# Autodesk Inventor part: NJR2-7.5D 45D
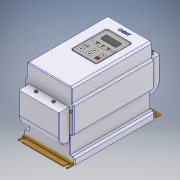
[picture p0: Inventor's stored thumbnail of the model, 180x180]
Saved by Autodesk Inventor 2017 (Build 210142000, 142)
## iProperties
Part Number: NJR2-7.5D 45D
Material: Типовые
Document SubType Name: Modeling
Designer: RSagdiev
Density: 1 g/cm^3
Appearance: По умолчанию
Author: RSagdiev
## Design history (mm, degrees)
sketch "Эскиз1"
  geometry: L1 (0, 0)-(14.471, 0) reference; L2 (0, 0)-(0, 21.118) reference; L3 (0, 0)-(230, 0); L4 (230, 0)-(230, 20); L5 (230, 190)-(0, 190); L6 (0, 190)-(0, 150); L7 (230, 20)-(0, 20); L8 (230, 70)-(0, 70); L9 (230, 70)-(230, 150); L10 (230, 20)-(230, 70); L11 (0, 70)-(0, 20); L12 (0, 20)-(0, 0); L13 (230, 150)-(0, 150); L14 (230, 150)-(230, 190); L15 (0, 150)-(0, 70)
  constraints: 30 end point, 17 parallel, 14 perpendicular, 3 horizontal, 2 vertical, 1 point on line
  dimensions: "d0" = 230 distance of L5.end L5.start; "d1" = 190 distance of L5.start L3.end; "d2" = 20 distance between parallel lines of L3 L7; "d3" = 50 distance between parallel lines of L8 L7; "d4" = 80 distance between parallel lines of L13 L8
extrude "Выдавливание1" new body sketch "Эскиз1" stored distance "d5" = 145; taper "d6" = 0 deg
extrude "Выдавливание2" join sketch "Эскиз1" stored distance "d7" = 120; taper "d8" = 0 deg
extrude "Выдавливание3" join sketch "Эскиз1" stored distance "d9" = 140; taper "d10" = 0 deg
extrude "Выдавливание4" join sketch "Эскиз1" stored distance "d11" = 130; taper "d12" = 0 deg
chamfer "Фаска1" distance "d13" = 5; stored, may be unused: second distance "d14" = 2, angle "d15" = 45 deg
sketch "Эскиз2"
  geometry: L1 (249, 0)-(234, 0); L2 (233, 1)-(233, 3); L3 (232, 4)-(-2, 4); L4 (-3, 3)-(-3, 1); L5 (-4, 0)-(-19, 0); L6 (230, 15)-(230, 0) reference; L7 (230, 0)-(0, 0) reference; L8 (0, 0)-(0, 15) reference; L9 (249, 3)-(236, 3); L10 (232, 7)-(-2, 7); L11 (-6, 3)-(-19, 3); L12 (-19, 0)-(-19, 3); L13 (249, 3)-(249, 0); A1 r 1 centre (-4, 1) between (-4, 0) and (-3, 1); A2 r 1 centre (-2, 3) between (-2, 4) and (-3, 3); A3 r 1 centre (234, 1) between (233, 1) and (234, 0); A4 r 1 centre (232, 3) between (233, 3) and (232, 4); A5 r 4 centre (232, 3) between (236, 3) and (232, 7); A6 r 4 centre (-2, 3) between (-2, 7) and (-6, 3); 6 further points
  constraints: 20 end point, 12 point on circle, 10 point on line, 8 tangent, 6 centre point, 4 perpendicular, 3 equal radius, 1 horizontal, 1 parallel, 4 other
  dimensions: "d16" = 4 distance of point (233, 0) point (233, 4); "d17" = 3 distance between parallel lines of L2 L6; "d18" = 4 distance between parallel lines of L7 L3; "d19" = 16 distance of point (233, 0) L1.start; "d20" = 16 distance of point (-3, 0) L5.end (= d19); "d21" = 4 distance of point (-3, 4) point (-3, 0) (derived); "d22" = 3 distance between parallel lines of L4 L8 (= d17); "d23" = 268 distance of L5.end L1.start (derived); "d24" = 1 radius of A1; "d25" = 3 distance between parallel lines of L1 L9
extrude "Выдавливание5" new body sketch "Эскиз2" stored distance "d26" = 143; taper "d27" = 0 deg
sketch "Эскиз4"
  geometry: L1 (260, 138)-(-30, 138); L2 (-30, 138)-(-30, 50); L3 (-30, 50)-(260, 50); L4 (260, 50)-(260, 138); L5 (0, 70)-(230, 70) reference; L6 (230, 190)-(230, 150) reference; L7 (230, 0)-(0, 0) reference; L8 (0, 150)-(230, 150) reference
  constraints: 8 end point, 2 parallel, 1 horizontal, 1 perpendicular
  dimensions: "d28" = 290 distance between parallel lines of L2 L4; "d187" = 20 distance between parallel lines of L5 L3; "d188" = 30 distance between parallel lines of L6 L4; "d189" = 50 distance between parallel lines of L7 L3 (derived); "d190" = 12 distance between parallel lines of L8 L1
extrude "Выдавливание6" join sketch "Эскиз4" stored distance "d32" = 115; taper "d33" = 0 deg
fillet "Сопряжение1" dims "d35" = 25
sketch "Эскиз5" dims "d44" = 10
  geometry: L1 (115, 0)-(0, 0) reference; L2 (115, 30)-(115, 0) reference; L3 (115, 30)-(0, 30) reference; L4 (0, 0)-(0, 30) reference; L5 (0, -260)-(115, -260) reference; L6 (0, -230)-(115, -230) reference; L7 (0, -260)-(0, -230) reference; L8 (115, -230)-(115, -260) reference; C1 r 4 at (20, 20); C2 r 4 at (35.833, 20); C3 r 4 at (51.667, 20); C4 r 4 at (67.5, 20); C5 r 4 at (83.333, 20); C6 r 4 at (99.167, 20); 1 further point
  constraints: 6 centre point, 1 horizontal, 10 other
  dimensions: "d36" = 8 diameter of C1; "d37" = 115 distance between parallel lines of L2 L4 (derived); "d38" = 20 distance from line of C1.centre L4; "d41" = 15.83333 distance of C1.centre C2.centre (= -0.166667 x d38 + 0.166667 x d37)
  node "Спроецированная петля1"
extrude "Выдавливание7" cut sketch "Эскиз5" distance "d46" = 20; taper "d47" = 0 deg
extrude "Выдавливание8" new body sketch "Эскиз5" distance "d48" = 20; taper "d49" = 0 deg
sketch "Эскиз6" dims "d50" = 12, "d56" = 10
  geometry: L1 (0, 6)-(5.196, 3); L2 (5.196, 3)-(5.196, -3); L3 (5.196, -3)-(0, -6); L4 (0, -6)-(-5.196, -3); L5 (-5.196, -3)-(-5.196, 3); L6 (-5.196, 3)-(0, 6); L7 (95, 10)-(-20, 10) reference; L8 (15.833, 6)-(21.029, 3); L9 (21.029, 3)-(21.029, -3); L10 (21.029, -3)-(15.833, -6); L11 (15.833, -6)-(10.637, -3); L12 (10.637, -3)-(10.637, 3); L13 (10.637, 3)-(15.833, 6); L14 (31.667, 6)-(36.863, 3); L15 (36.863, 3)-(36.863, -3); L16 (36.863, -3)-(31.667, -6); L17 (31.667, -6)-(26.471, -3); L18 (26.471, -3)-(26.471, 3); L19 (26.471, 3)-(31.667, 6); L20 (47.5, 6)-(52.696, 3); L21 (52.696, 3)-(52.696, -3); L22 (52.696, -3)-(47.5, -6); L23 (47.5, -6)-(42.304, -3); L24 (42.304, -3)-(42.304, 3); L25 (42.304, 3)-(47.5, 6); L26 (63.333, 6)-(68.529, 3); L27 (68.529, 3)-(68.529, -3); L28 (68.529, -3)-(63.333, -6); L29 (63.333, -6)-(58.137, -3); L30 (58.137, -3)-(58.137, 3); L31 (58.137, 3)-(63.333, 6); L32 (79.167, 6)-(84.363, 3); L33 (84.363, 3)-(84.363, -3); L34 (84.363, -3)-(79.167, -6); L35 (79.167, -6)-(73.971, -3); L36 (73.971, -3)-(73.971, 3); L37 (73.971, 3)-(79.167, 6); 13 further points
  constraints: 72 end point, 6 coincident, 6 horizontal, 6 vertical alignment, 95 other
  dimensions: "d53" = 15.83333 distance of point (0, 0) point (15.833, 0) (= -0.166667 x d38 + 0.166667 x d37)
extrude "Выдавливание9" join sketch "Эскиз6" distance "d58" = 5; taper "d59" = 0 deg
sketch "Эскиз7" dims "d185" = 10
  geometry: L1 (2.964, 2.686)-(3.808, -1.224); L2 (3.808, -1.224)-(0.844, -3.91); L3 (0.844, -3.91)-(-2.964, -2.686); L4 (-2.964, -2.686)-(-3.808, 1.224); L5 (-3.808, 1.224)-(-0.844, 3.91); L6 (-0.844, 3.91)-(2.964, 2.686); L7 (95, 10)-(-20, 10) reference; L8 (23.764, 2.686)-(24.608, -1.224); L9 (24.608, -1.224)-(21.644, -3.91); L10 (21.644, -3.91)-(17.836, -2.686); L11 (17.836, -2.686)-(16.992, 1.224); L12 (16.992, 1.224)-(19.956, 3.91); L13 (19.956, 3.91)-(23.764, 2.686); L14 (44.564, 2.686)-(45.408, -1.224); L15 (45.408, -1.224)-(42.444, -3.91); L16 (42.444, -3.91)-(38.636, -2.686); L17 (38.636, -2.686)-(37.792, 1.224); L18 (37.792, 1.224)-(40.756, 3.91); L19 (40.756, 3.91)-(44.564, 2.686); L20 (65.364, 2.686)-(66.208, -1.224); L21 (66.208, -1.224)-(63.244, -3.91); L22 (63.244, -3.91)-(59.436, -2.686); L23 (59.436, -2.686)-(58.592, 1.224); L24 (58.592, 1.224)-(61.556, 3.91); L25 (61.556, 3.91)-(65.364, 2.686); L26 (86.164, 2.686)-(87.008, -1.224); L27 (87.008, -1.224)-(84.044, -3.91); L28 (84.044, -3.91)-(80.236, -2.686); L29 (80.236, -2.686)-(79.392, 1.224); L30 (79.392, 1.224)-(82.356, 3.91); L31 (82.356, 3.91)-(86.164, 2.686); L32 (106.964, 2.686)-(107.808, -1.224); L33 (107.808, -1.224)-(104.844, -3.91); L34 (104.844, -3.91)-(101.036, -2.686); L35 (101.036, -2.686)-(100.192, 1.224); L36 (100.192, 1.224)-(103.156, 3.91); L37 (103.156, 3.91)-(106.964, 2.686); C1 r 6 at (0, 0) reference; A1 r 4 centre (0, 0) between (2.964, 2.686) and (-2.964, -2.686); A2 r 4 centre (20.8, 0) between (23.764, 2.686) and (17.836, -2.686); A3 r 4 centre (41.6, 0) between (44.564, 2.686) and (38.636, -2.686); A4 r 4 centre (62.4, 0) between (65.364, 2.686) and (59.436, -2.686); A5 r 4 centre (83.2, 0) between (86.164, 2.686) and (80.236, -2.686); A6 r 4 centre (104, 0) between (106.964, 2.686) and (101.036, -2.686); 1 further point
  constraints: 72 end point, 36 point on circle, 6 centre point, 5 equal length, 1 horizontal, 70 other
  dimensions: "d179" = 2 radial gap between concentric circles of C1 A1; "d182" = 20.8 distance of L1.start L8.start
extrude "Выдавливание10" cut sketch "Эскиз7" distance "d66" = 1.5; taper "d67" = 0 deg
fillet "Сопряжение2" dims "d68" = 2
sketch "Эскиз8"
  geometry: L1 (0, -268)-(143, -268) reference; L2 (143, 0)-(0, 0) reference; L3 (143, 0)-(143, -15) reference; L4 (0, -15)-(0, 0) reference; L5 (7.5, -9)-(7.5, -14); L6 (135.5, -9)-(135.5, -14); L7 (7.5, -9)-(135.5, -9); L8 (7.5, -259)-(7.5, -268); L9 (4, -259)-(4, -268); L10 (11, -268)-(11, -259); L11 (7.5, -9)-(7.5, -259); L12 (7.5, -259)-(135.5, -259); L13 (135.5, -9)-(135.5, -259); L14 (135.5, -259)-(135.5, -268); L15 (132, -259)-(132, -268); L16 (139, -268)-(139, -259); A1 r 3.5 centre (7.5, -9) between (10.779, -10.225) and (4.221, -10.225); A2 r 5 centre (7.5, -14) between (4.221, -10.225) and (10.779, -10.225); A3 r 3.5 centre (135.5, -9) between (138.779, -10.225) and (132.221, -10.225); A4 r 5 centre (135.5, -14) between (132.221, -10.225) and (138.779, -10.225); A5 r 3.5 centre (7.5, -259) between (11, -259) and (4, -259); A6 r 3.5 centre (7.5, -268) between (4, -268) and (11, -268); A7 r 3.5 centre (135.5, -259) between (139, -259) and (132, -259); A8 r 3.5 centre (135.5, -268) between (132, -268) and (139, -268); 5 further points
  constraints: 28 end point, 16 point on circle, 8 centre point, 8 tangent, 4 vertical, 3 coincident, 2 horizontal, 2 midpoint, 2 parallel, 2 perpendicular, 2 point on line
  dimensions: "d69" = 128 distance of point (135.5, -9) point (7.5, -9); "d70" = 250 distance of L8.start point (7.5, -9); "d71" = 268 distance between parallel lines of L1 L2 (derived); "d72" = 9 distance from line of L2 point (7.5, -9) (= -0.5 x d70 + 0.5 x d71); "d73" = 143 distance between parallel lines of L3 L4 (derived); "d74" = 7.5 distance from line of L4 point (7.5, -9) (= -0.5 x d69 + 0.5 x d73); "d75" = 7 diameter of A1; "d76" = 10 diameter of A2; "d77" = 5 distance of L5.start L5.end; "d78" = 7 diameter of A3; "d79" = 10 diameter of A4; "d80" = 5 distance of L6.start L6.end; "d81" = 7 diameter of A6; "d82" = 7 diameter of A8
extrude "Выдавливание11" cut sketch "Эскиз8" distance "d83" = 5.5; taper "d84" = 0 deg
fillet "Сопряжение3" dims "d85" = 2
sketch "Эскиз9"
  geometry: L1 (125, 0)-(5, 0); L2 (5, 226)-(125, 226); L3 (33, 193)-(97, 193); L4 (100, 190)-(100, 96); L5 (97, 93)-(33, 93); L6 (30, 96)-(30, 190); L7 (97, 195)-(33, 195); L8 (28, 190)-(28, 96); L9 (33, 91)-(97, 91); L10 (102, 96)-(102, 190); L11 (125, 226)-(125, 0); L12 (5, 0)-(5, 226); A1 r 3 centre (33, 190) between (33, 193) and (30, 190); A2 r 3 centre (97, 190) between (100, 190) and (97, 193); A3 r 3 centre (97, 96) between (97, 93) and (100, 96); A4 r 3 centre (33, 96) between (30, 96) and (33, 93); A5 r 5 centre (33, 190) between (33, 195) and (28, 190); A6 r 5 centre (33, 96) between (28, 96) and (33, 91); A7 r 5 centre (97, 96) between (97, 91) and (102, 96); A8 r 5 centre (97, 190) between (102, 190) and (97, 195); 4 further points
  constraints: 24 end point, 16 point on circle, 8 centre point, 8 tangent, 6 point on line, 4 parallel, 3 equal radius, 2 perpendicular, 1 horizontal, 7 other
  dimensions: "d86" = 70 distance of point (100, 93) point (30, 93); "d87" = 100 distance of point (100, 193) point (100, 93); "d90" = 33 distance between parallel lines of L2 L3 (computed from d89, d87); "d92" = 3 radius of A1; "d93" = 2 distance between parallel lines of L3 L7
extrude "Выдавливание12" cut sketch "Эскиз9" distance "d94" = 25; taper "d95" = 0 deg
extrude "Выдавливание13" new body sketch "Эскиз9" distance "d96" = 25; taper "d97" = 0 deg
sketch "Эскиз10"
  geometry: L1 (30, 190)-(30, 150.574); L2 (33, 93)-(97, 93); L3 (100, 96)-(100, 150.574); L4 (97, 193)-(33, 193); L5 (97, 193)-(33, 193) reference; L6 (30, 190)-(30, 96) reference; L7 (30, 150.574)-(30, 96); L8 (100, 150.574)-(100, 190); L9 (45.628, 161.287)-(84.628, 161.287); L10 (87.628, 164.287)-(87.628, 176.287); L11 (84.628, 179.287)-(45.628, 179.287); L12 (42.628, 176.287)-(42.628, 164.287); L13 (42.628, 161.287)-(87.628, 179.287); L14 (87.628, 161.287)-(42.628, 179.287); A1 r 3 centre (33, 96) between (30, 96) and (33, 93); A2 r 3 centre (97, 96) between (97, 93) and (100, 96); A3 r 3 centre (97, 190) between (100, 190) and (97, 193); A4 r 3 centre (33, 190) between (33, 193) and (30, 190); A5 r 55 centre (65, 193) between (30, 150.574) and (100.197, 150.737); A6 r 3 centre (45.628, 176.287) between (45.628, 179.287) and (42.628, 176.287); A7 r 3 centre (45.628, 164.287) between (42.628, 164.287) and (45.628, 161.287); A8 r 3 centre (84.628, 176.287) between (87.628, 176.287) and (84.628, 179.287); A9 r 3 centre (84.628, 164.287) between (84.628, 161.287) and (87.628, 164.287); 2 further points
  constraints: 20 end point, 11 point on circle, 9 centre point, 9 point on line, 8 tangent, 3 equal radius, 3 midpoint, 2 parallel, 1 horizontal, 1 perpendicular
  dimensions: "d98" = 55 radius of A5; "d99" = 45 distance of L14.end L13.end; "d100" = 18 distance of L13.end L14.start; "d101" = 22.7132 distance from line of L4 point (65.128, 170.287); "d102" = 35.1281 distance from line of L1 point (65.128, 170.287); "d103" = 3 radius of A6 (derived)
extrude "Выдавливание14" cut sketch "Эскиз10" distance "d104" = 1; taper "d105" = 0 deg
sketch "Эскиз11"
  geometry: L1 (30, 150.574)-(30, 96) reference; L2 (33, 93)-(97, 93) reference; L3 (100, 96)-(100, 150.574) reference; L4 (30, 150.574)-(30, 96) reference; L5 (30, 123)-(100, 123); L6 (100, 96)-(100, 150.574) reference; L7 (30, 108)-(100, 108); L8 (33, 93)-(97, 93) reference; L9 (41.667, 93)-(41.667, 143.195); L10 (88.333, 93)-(88.333, 143.195); L11 (65, 93)-(65, 138); L12 (36.667, 128)-(46.667, 128); L13 (46.667, 128)-(46.667, 118); L14 (46.667, 118)-(36.667, 118); L15 (36.667, 118)-(36.667, 128); L16 (36.667, 128)-(46.667, 118); L17 (46.667, 128)-(36.667, 118); L18 (36.667, 113)-(46.667, 113); L19 (46.667, 113)-(46.667, 103); L20 (46.667, 103)-(36.667, 103); L21 (36.667, 103)-(36.667, 113); L22 (36.667, 113)-(46.667, 103); L23 (46.667, 113)-(36.667, 103); L24 (60, 128)-(70, 128); L25 (70, 128)-(70, 118); L26 (70, 118)-(60, 118); L27 (60, 118)-(60, 128); L28 (60, 128)-(70, 118); L29 (70, 128)-(60, 118); L30 (60, 113)-(70, 113); L31 (70, 113)-(70, 103); L32 (70, 103)-(60, 103); L33 (60, 103)-(60, 113); L34 (60, 113)-(70, 103); L35 (70, 113)-(60, 103); L36 (83.333, 128)-(93.333, 128); L37 (93.333, 128)-(93.333, 118); L38 (93.333, 118)-(83.333, 118); L39 (83.333, 118)-(83.333, 128); L40 (83.333, 128)-(93.333, 118); L41 (93.333, 128)-(83.333, 118); L42 (83.333, 113)-(93.333, 113); L43 (93.333, 113)-(93.333, 103); L44 (93.333, 103)-(83.333, 103); L45 (83.333, 103)-(83.333, 113); L46 (83.333, 113)-(93.333, 103); L47 (93.333, 113)-(83.333, 103); L48 (46.767, 128.1)-(36.567, 128.1); L49 (36.567, 128.1)-(36.567, 117.9); L50 (36.567, 117.9)-(46.767, 117.9); L51 (46.767, 117.9)-(46.767, 128.1); L52 (70.1, 128.1)-(59.9, 128.1); L53 (59.9, 128.1)-(59.9, 117.9); L54 (59.9, 117.9)-(70.1, 117.9); L55 (70.1, 117.9)-(70.1, 128.1); L56 (93.433, 128.1)-(83.233, 128.1); L57 (83.233, 128.1)-(83.233, 117.9); L58 (83.233, 117.9)-(93.433, 117.9); L59 (93.433, 117.9)-(93.433, 128.1); L60 (46.767, 113.1)-(36.567, 113.1); L61 (36.567, 113.1)-(36.567, 102.9); L62 (36.567, 102.9)-(46.767, 102.9); L63 (46.767, 102.9)-(46.767, 113.1); L64 (70.1, 113.1)-(59.9, 113.1)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; A1 r 55 centre (65, 193) between (30, 150.574) and (100, 150.574) reference; A2 r 3 centre (33, 96) between (30, 96) and (33, 93) reference; A3 r 3 centre (97, 96) between (97, 93) and (100, 96) reference; A4 r 55 centre (65, 193) between (30, 150.574) and (100, 150.574) reference; 8 further points
  constraints: 130 end point, 24 parallel, 16 midpoint, 16 point on line, 14 perpendicular, 7 horizontal, 4 point on circle, 1 vertical, 18 other
  dimensions: "d106" = 70 distance between parallel lines of L3 L1 (derived); "d107" = 45 distance from line of L2 L11.end (derived); "d108" = 15 distance between parallel lines of L7 L5 (= 0.333333 x d107); "d109" = 15 distance from line of L11.end L5 (= 0.333333 x d107); "d110" = 23.33333 distance between parallel lines of L11 L10 (= 0.333333 x d106); "d111" = 23.33333 distance between parallel lines of L11 L9 (= d110); "d112" = 10 distance of L13.end L14.end; "d113" = 10 distance of L12.end L13.end; "d114" = 10 distance of L19.end L20.end; "d115" = 10 distance of L18.end L19.end; "d116" = 10 distance of L25.end L26.end; "d117" = 10 distance of L24.end L25.end; "d118" = 10 distance of L31.end L32.end; "d119" = 10 distance of L30.end L31.end; "d120" = 10 distance of L37.end L38.end; "d121" = 10 distance of L36.end L37.end; "d122" = 10 distance of L43.end L44.end; "d123" = 10 distance of L42.end L43.end; "d124" = 0.1 distance between parallel lines of L12 L48; "d125" = 0.1 distance between parallel lines of L24 L52; "d126" = 0.1 distance between parallel lines of L36 L56; "d127" = 0.1 distance between parallel lines of L18 L60; "d128" = 0.1 distance between parallel lines of L30 L64; "d129" = 0.1 distance between parallel lines of L42 L68
extrude "Выдавливание15" cut sketch "Эскиз11" distance "d130" = 3; taper "d131" = 0 deg
sketch "Эскиз12"
  geometry: L1 (100, 96)-(100, 150.574) reference; L2 (50, 144.701)-(80, 144.701); C1 r 1.5 at (65, 144.701); C2 r 1.5 at (80, 144.701); C3 r 1.5 at (50, 144.701); C4 r 1.6 at (50, 144.701); C5 r 1.6 at (65, 144.701); C6 r 1.6 at (80, 144.701); A1 r 55 centre (65, 193) between (30, 150.574) and (100, 150.574) reference; 1 further point
  constraints: 6 centre point, 2 end point, 1 coincident, 1 horizontal, 1 midpoint
  dimensions: "d132" = 3 diameter of C1; "d133" = 3 diameter of C2; "d134" = 3 diameter of C3; "d135" = 48.29941 distance of A1.centre C1.centre; "d136" = 35 distance from line of L1 C1.centre; "d137" = 15 distance of C1.centre C2.centre; "d138" = 15 distance of C1.centre L2.start; "d139" = 0.1 radial gap between concentric circles of C3 C4; "d140" = 0.1 radial gap between concentric circles of C1 C5; "d141" = 0.1 radial gap between concentric circles of C2 C6
extrude "Выдавливание16" cut sketch "Эскиз12" distance "d142" = 3; taper "d143" = 0 deg
sketch "Эскиз13"
  geometry: L1 (45, 150.348)-(102.075, 150.348); L2 (102.075, 150.348)-(102.075, 146.701); L3 (102.075, 146.701)-(45, 146.701); L4 (45, 146.701)-(45, 150.348); C1 r 1.5 at (50, 144.701) reference; 1 further point
  constraints: 2 other
  dimensions: "d144" = 2 vertical distance of L3.end C1.centre; "d145" = 5 horizontal distance of C1.centre L3.end
feature "Рельеф1" sketch "Эскиз13" dims "d10" = 0, "d146" = 0.1, "d147" = 0
sketch "Эскиз14"
  geometry: L1 (36.734, 124.406)-(51.145, 124.406); L2 (51.145, 124.406)-(51.145, 120.906); L3 (51.145, 120.906)-(36.734, 120.906); L4 (36.734, 120.906)-(36.734, 124.406); L5 (38.873, 106.059)-(38.873, 109.559); L6 (38.873, 109.559)-(53.285, 109.559); L7 (53.285, 109.559)-(53.285, 106.059); L8 (53.285, 106.059)-(38.873, 106.059); L9 (84.699, 105.985)-(84.699, 109.485); L10 (84.699, 109.485)-(99.11, 109.485); L11 (99.11, 109.485)-(99.11, 105.985); L12 (99.11, 105.985)-(84.699, 105.985); L13 (85.21, 120.906)-(85.21, 124.406); L14 (85.21, 124.406)-(99.621, 124.406); L15 (99.621, 124.406)-(99.621, 120.906); L16 (99.621, 120.906)-(85.21, 120.906); 1 further point
  constraints: 8 other
feature "Рельеф2" dims "d10" = 0, "d148" = 0.1, "d149" = 0
feature "Рельеф3" dims "d10" = 0, "d150" = 0.1, "d151" = 0
feature "Рельеф4" dims "d10" = 0, "d152" = 0.1, "d153" = 0
feature "Рельеф5" dims "d10" = 0, "d154" = 0.1, "d155" = 0
sketch "Эскиз15" dims "d156" = 6, "d157" = 6
  geometry: L1 (60, 128)-(60, 118) reference; L2 (60, 118)-(70, 118) reference; L3 (70, 118)-(70, 128) reference; L4 (70, 128)-(60, 128) reference; L5 (60, 113)-(60, 103) reference; L6 (60, 103)-(70, 103) reference; L7 (70, 103)-(70, 113) reference; L8 (70, 113)-(60, 113) reference; L9 (60, 118)-(70, 128); L10 (60, 128)-(70, 118); L11 (60, 113)-(70, 103); L12 (70.1, 113.1)-(70.1, 102.9) reference; L13 (70.1, 113.1)-(60, 103); L14 (65.05, 126)-(67.573, 121.457); L15 (67.573, 121.457)-(62.377, 121.544); L16 (62.377, 121.544)-(65.05, 126); L17 (65.05, 105.05)-(62.452, 109.55); L18 (62.452, 109.55)-(67.648, 109.55); L19 (67.648, 109.55)-(65.05, 105.05); 5 further points
  constraints: 20 end point, 2 coincident, 2 midpoint, 2 perpendicular, 1 parallel, 1 vertical alignment, 19 other
  node "Спроецированная петля11"
  node "Спроецированная петля12"
feature "Рельеф6" dims "d10" = 0, "d158" = 0.1, "d159" = 0
feature "Рельеф7" dims "d10" = 0, "d160" = 0.1, "d161" = 0
sketch "Эскиз16"
  geometry: L1 (2, -30)-(113, -30) reference; L2 (0, 0)-(115, 0) reference; L3 (130, -10)-(0, -10); L4 (0, -28)-(0, -5) reference; L5 (113, 260)-(2, 260) reference; L6 (115, 230)-(0, 230) reference; L7 (115, 0)-(115, -28) reference; L8 (0, -28)-(0, 0) reference; L9 (0, 230)-(0, 258) reference; L10 (115, 258)-(115, 230) reference; C1 r 4 at (30, -10); C2 r 4 at (80, -10); C3 r 4 at (130, -10); A1 r 2 centre (2, -28) between (0, -28) and (2, -30) reference; A2 r 2 centre (113, -28) between (113, -30) and (115, -28) reference; A3 r 2 centre (113, 258) between (115, 258) and (113, 260) reference; A4 r 2 centre (2, 258) between (2, 260) and (0, 258) reference; 1 further point
  constraints: 3 centre point, 3 point on line, 2 end point, 1 horizontal
  dimensions: "d162" = 8 diameter of C1; "d163" = 8 diameter of C2; "d164" = 8 diameter of C3; "d166" = 20 distance from line of L3.start L1; "d167" = 50 distance of C2.centre L3.start; "d168" = 50 distance of C1.centre C2.centre
extrude "Выдавливание17" new body sketch "Эскиз16" distance "d169" = 3; taper "d170" = 0 deg
sketch "Эскиз17"
  geometry: L1 (-28, -20)-(83, -20) reference; L2 (-30, 10)-(85, 10) reference; L3 (0, 3)-(2.598, 1.5); L4 (2.598, 1.5)-(2.598, -1.5); L5 (2.598, -1.5)-(0, -3); L6 (0, -3)-(-2.598, -1.5); L7 (-2.598, -1.5)-(-2.598, 1.5); L8 (-2.598, 1.5)-(0, 3); L9 (50, 3)-(52.598, 1.5); L10 (52.598, 1.5)-(52.598, -1.5); L11 (52.598, -1.5)-(50, -3); L12 (50, -3)-(47.402, -1.5); L13 (47.402, -1.5)-(47.402, 1.5); L14 (47.402, 1.5)-(50, 3); L15 (100, 3)-(102.598, 1.5); L16 (102.598, 1.5)-(102.598, -1.5); L17 (102.598, -1.5)-(100, -3); L18 (100, -3)-(97.402, -1.5); L19 (97.402, -1.5)-(97.402, 1.5); L20 (97.402, 1.5)-(100, 3); L21 (83, 270)-(-28, 270) reference; L22 (85, 240)-(-30, 240) reference; L23 (85, 10)-(85, -18) reference; L24 (-30, -18)-(-30, 10) reference; L25 (-30, 240)-(-30, 268) reference; L26 (85, 268)-(85, 240) reference; C1 r 4 at (0, 0) reference; C2 r 4 at (50, 0) reference; C3 r 4 at (100, 0) reference; C4 r 4 at (50, 0) reference; A1 r 2 centre (-28, -18) between (-30, -18) and (-28, -20) reference; A2 r 2 centre (83, -18) between (83, -20) and (85, -18) reference; A3 r 2 centre (83, 268) between (85, 268) and (83, 270) reference; A4 r 2 centre (-28, 268) between (-28, 270) and (-30, 268) reference; 4 further points
  constraints: 36 end point, 3 coincident, 3 vertical alignment, 45 other
  dimensions: "d171" = 1 dimension on C1; "d172" = 1 dimension on C2; "d173" = 1 dimension on C3
extrude "Выдавливание18" cut sketch "Эскиз17" distance "d174" = 0.5; taper "d175" = 0 deg
fillet "Сопряжение4" dims "d176" = 1
sketch "Эскиз18"
  geometry: L1 (46.683, 214.728)-(62.561, 214.728); L2 (62.561, 214.728)-(62.561, 211.091); L3 (62.561, 211.091)-(46.683, 211.091); L4 (46.683, 211.091)-(46.683, 214.728); 1 further point
  constraints: 2 other
feature "Рельеф8" sketch "Эскиз18" dims "d10" = 0, "d177" = 0.1, "d178" = 0
node "Твердое тело1"
node "Твердое тело2"
node "Твердое тело3"
node "Твердое тело4"
node "Спроецированная петля10"
node "Спроецированная петля13"
node "Твердое тело5"
node "Спроецированная петля14"
node "Спроецированная петля15"
node "Спроецированная петля16"
node "Спроецированная петля17"
other parameters: "d89" = 226 (derived)
